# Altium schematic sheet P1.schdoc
size 178 x 97 mm; Symbol: Drawing-Symbol_A4; Company: 嘉立创EDA; Version: V1.0; Page Size: A4; @Project Name: PCB; @Update Date: 2026-07-19; @Create Date: 2026-07-19; Device: Drawing-Symbol_A4; @Board Name: Board1; @Page Name: P1; @Create Time: 23:37:44; @Page Count: 1; @Page No: 1; @Schematic Name: Schematic1; @Update Time: 23:37:44; @Assembly Variant: Basic; Border: 0; Title Block Position: 3; Size: A4; Width: 1170; Height: 825; Region Start: 1; X Region Count: 6; Y Region Count: 4; Blade Width: 10
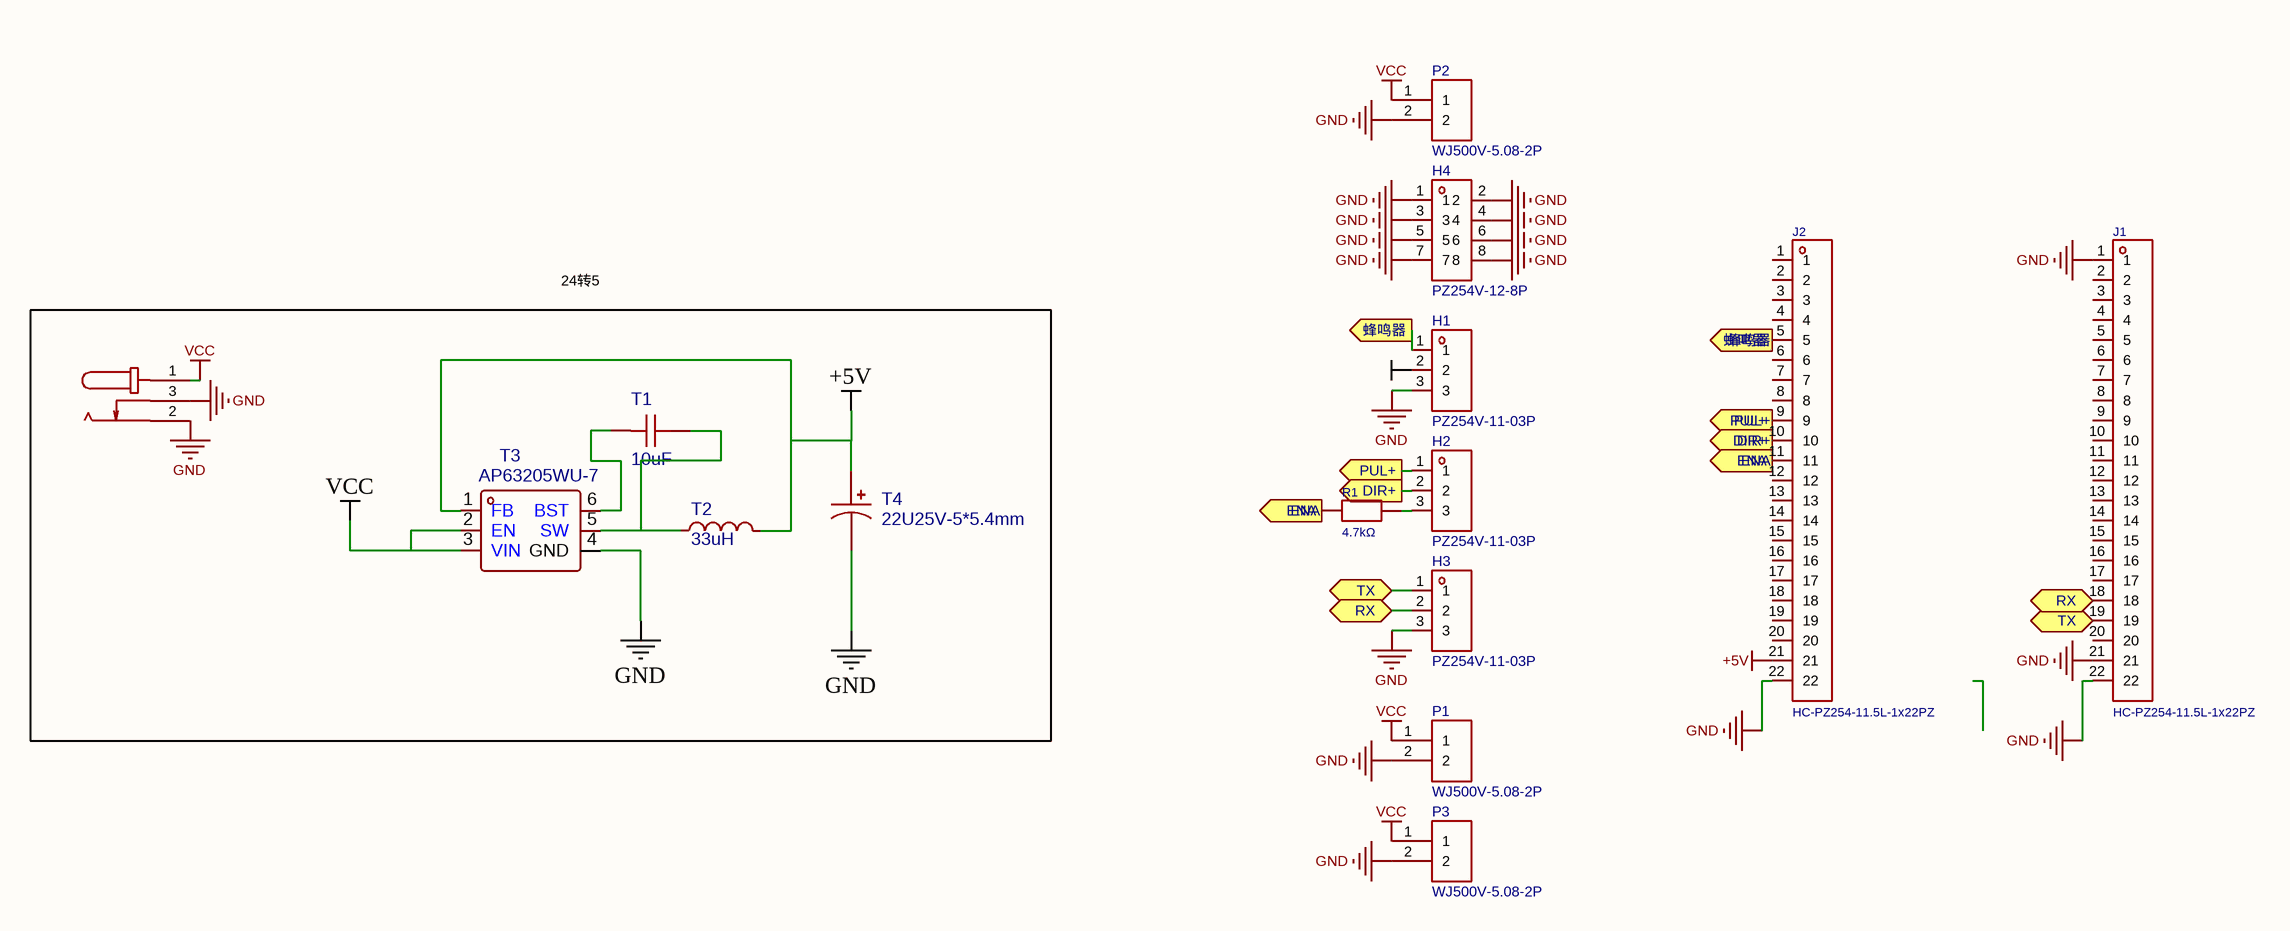
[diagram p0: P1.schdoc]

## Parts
DC1  DC005  [DC-IN-TH_DC005]  (value not drawn)
H1  PZ254V-11-03P  [HDR-TH_3P-P2.54-V-M_PZ254V-11-03P]
H2  PZ254V-11-03P  [HDR-TH_3P-P2.54-V-M_PZ254V-11-03P]
H3  PZ254V-11-03P  [HDR-TH_3P-P2.54-V-M_PZ254V-11-03P]
H4  PZ254V-12-8P  [HDR-TH_8P-P2.54-V-M-R2-C4-S2.54]
J1  HC-PZ254-11.5L-1x22PZ  [HDR-TH_22P-P2.54-V-M]
J2  HC-PZ254-11.5L-1x22PZ  [HDR-TH_22P-P2.54-V-M]
P1  WJ500V-5.08-2P  [CONN-TH_2P-P5.00_WJ500V-5.08-2P]
P2  WJ500V-5.08-2P  [CONN-TH_2P-P5.00_WJ500V-5.08-2P]
P3  WJ500V-5.08-2P  [CONN-TH_2P-P5.00_WJ500V-5.08-2P]
R1  4.7kΩ  [R0603]
T1  10uF  [C0603]
T2  33uH  [IND-SMD_L7.0-W6.6_FXL0650]
T3  AP63205WU-7  [TSOT-23-6_L2.9-W1.6-P0.95-LS2.8-BL]
T4  22U25V-5*5.4mm  [CAP-SMD_BD5.0-L5.3-W5.3-LS6.0-FD]

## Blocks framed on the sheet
24转5: DC1 T1-T4

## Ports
DIR+ (out), ENA (out), PUL+ (out), RX (bidir), TX (bidir), 蜂鸣器 (out)

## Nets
+5V: J2.21 T2.2 T3.1(FB) T4.1
GND: DC1.2 DC1.3 H1.3 H3.3 H4.1 H4.2 H4.3 H4.4 H4.5 H4.6 H4.7 H4.8 J1.1 J1.21 J1.22 J2.22 P1.2 P2.2 P3.2 T3.4(GND) T4.2
VCC: DC1.1 P1.1 P2.1 P3.1 T3.2(EN) T3.3(VIN)
DIR+: H2.2 J2.10 ; port DIR+
ENA: J2.11 R1.1 ; port ENA
PUL+: H2.1 J2.9 ; port PUL+
RX: H3.2 J1.18 ; port RX
TX: H3.1 J1.19 ; port TX
蜂鸣器: H1.1 J2.5 ; port 蜂鸣器
NetH2_3: H2.3 R1.2
NetT1_1: T1.1 T2.1 T3.5(SW)
NetT1_2: T1.2 T3.6(BST)

Not connected (* = marked no-connect by the designer): H1 2; J1 2 3 4 5 6 7 8 9 10 11 12 13 14 15 16 17 20; J2 1 2 3 4 6 7 8 12 13 14 15 16 17 18 19 20

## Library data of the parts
DC1 = DC005: 连接器类型:DC电源插座;安装方式:弯插;触点内径:2mm;触点外径:6.3mm;额定电流:500mA;额定电压:12V;工作温度:-30℃~+70℃;; Manufacturer: SHOU HAN(首韩); Symbol: DC005_C431533; Add into BOM: yes; 3D Model Transform: 366.141,553.149,0,270,0,0,-141.734,88.583,-149.606; 3D Model: f168fe383f964e0ea2af0127ff6ac7b4; Connector Type: DC电源插座; Inside Contact Diameter: 2mm; Outside Contact Diameter: 6.3mm; Current Rating: 500mA; Voltage Rating (Max): 12V
H1-H3 = PZ254V-11-03P: 插针结构:1x3P;间距:2.54mm;行距:-;圆针/方针:方针;安装方式:直插;排数:单排;总PIN位数:3P;额定电流:3A;额定电压:250V;配合针长度:6mm;塑高:2.5mm;端接针长度:3mm;工作温度:-40℃~+105℃;颜色:黑色;; Manufacturer: XFCN(兴飞); Symbol: PZ254V-11-03P_C2937625; AddInBom: yes; ModelId: bd28a638fbd247be9398fd5d39c366ec0819f05c4eef4c71ace90d822a990e87; ModelTransform: 300.3931,100,0,0,0,0,0,0,-118.11; Pin Structure: 1x3P; Pitch: 2.54mm; Circluar Pins/Square Pins: 方针; Current Rating: 3A; Voltage Rating (Max): 250V
H4 = PZ254V-12-8P: 插针结构:2x4P;间距:2.54mm;行距:2.54mm;圆针/方针:方针;安装方式:直插;排数:双排;总PIN位数:8P;额定电流:-;额定电压:-;配合针长度:6mm;塑高:2.5mm;端接针长度:3mm;触头材质:黄铜;触头镀层:-;工作温度:-40℃~+105℃;颜色:黑色;; Manufacturer: XFCN(兴飞); AddInBom: yes; ModelId: 9655140a9899454ea9d6a6732d55fb0e0819f05c4eef4c71ace90d822a990e87; ModelName: HDR-TH_8P-P2.54-M-LI-2X4P; ModelTransform: 399.999,200,0,0,0,0,0,0,-118.11; Pin Structure: 2x4P; Pitch: 2.54mm; Circluar Pins/Square Pins: 方针
J1 J2 = HC-PZ254-11.5L-1x22PZ: 插针结构:1x22P;间距:2.54mm;行距:-;圆针/方针:方针;安装方式:直插;排数:单排;总PIN位数:22P;额定电流:3A;额定电压:-;配合针长度:6mm;塑高:2.5mm;端接针长度:3mm;触头材质:黄铜;触头镀层:金;工作温度:-40℃~+105℃;颜色:黑色;; Manufacturer: HC(虹成电子); Add into BOM: yes; 3D Model: 875f4c094945453e8148e92095c9b8a7; 3D Model Transform: 2199.99552,98.425,0,0,0,0,0,0,-118.11; Pin Structure: 1x22P; Pitch: 2.54mm; Circluar Pins/Square Pins: 方针; Current Rating: 3A; ModelName: HDR-TH_22P-P2.54-M-LI-1X22P
P1 = WJ500V-5.08-2P: 结构:1x2P;间距:5.08mm;颜色:绿色;安装方式:直插;额定电流:18A;额定电压:250V;排数:1;线规 - AWG:14~30;线规 - 平方毫米:2.5;每排PIN数:2;触头材质:-;触头镀层:-;工作温度范围:-40℃~+105℃;焊接温度(最大值):-;; Manufacturer: KANGNEX(康奈克斯电气); Symbol: WJ500V-5.08-2P-14-00A; AddInBom: yes; ModelId: 0f4a503c8d3b4ae19ed61267f5e9a1d70819f05c4eef4c71ace90d822a990e87; ModelTransform: 423.621,393.7,0,0,0,0,-11.811,19.685,-137.795; Structure: 1x2P; Pitch: 5.08mm; Current Rating (Max): 18A; Voltage Rating (Max): 250V; Wire Gauge - AWG: 14~30; Wire Gauge - mm2: 2.5; Number of PINs Per Row: 2; Screw Specification: M2.5
P2 P3 = WJ500V-5.08-2P: 结构:1x2P;间距:5.08mm;颜色:绿色;安装方式:直插;额定电流:18A;额定电压:250V;排数:1;线规 - AWG:14~30;线规 - 平方毫米:2.5;每排PIN数:2;触头材质:-;触头镀层:-;工作温度范围:-40℃~+105℃;焊接温度(最大值):-;; Manufacturer: KANGNEX(康奈克斯电气); Symbol: WJ500V-5.08-2P-14-00A; 3D Model: 0f4a503c8d3b4ae19ed61267f5e9a1d70819f05c4eef4c71ace90d822a990e87; 3D Model Transform: 423.621,393.7,0,0,0,0,-11.811,19.685,-137.795; Structure: 1x2P; Pitch: 5.08mm; Current Rating (Max): 18A; Voltage Rating (Max): 250V; Wire Gauge - AWG: 14~30; Wire Gauge - mm2: 2.5; Number of PINs Per Row: 2; Screw Specification: M2.5; AddInBom: yes
R1 = FRR0603F4701TS: 电阻类型:厚膜电阻;阻值:4.7kΩ;精度:±1%;功率:100mW;工作电压:75V;温度系数:±100ppm/℃;; Manufacturer: FOJAN(富捷); AddInBom: yes; ModelId: fc143cca1e79419f9cd78b61e9279f080819f05c4eef4c71ace90d822a990e87; ModelTransform: 31.8897,63.7794,0,90,0,0,0,0,0; Tolerance: ±1%; Power(Watts): 100mW; Voltage-Supply(Max): 75V
T1 = 0603X106M100CT: 容值:10uF;精度:±20%;额定电压:10V;温度系数:X5R;; Manufacturer: Walsin(华新科); Add into BOM: yes; 3D Model Transform: 62.992,31.496,0,0,0,0,0,0,0; 3D Model: ac125912035d415993ca9572d50418b1; Tolerance: ±20%; Voltage Rating: 10V; Temperature Coefficient: X5R; ModelName: C0603_L1.6-W0.8-H0.8
T2 = FXL0650-330-M: 电感值:33uH;精度:±20%;额定电流:2.3A;饱和电流(Isat):3A;类型:一体成型电感;; Manufacturer: cjiang(长江微电); Add into BOM: yes; 3D Model Transform: 275.59,259.842,0,0,0,0,0,0,0; 3D Model: 79e71cf45778409db1a3f3d6d59bfe87; Tolerance: ±20%; Current Rating: 2.3A; Current - Saturation(Isat): 3A; DC Resistance(DCR): 190mΩ; Type: 一体成型电感; ModelName: IND-SMD_L7.0-W6.6-H4.8_FXL0650
T3 = AP63205WU-7: Manufacturer: DIODES(美台); Add into BOM: yes; Origin 3D Model Title: TSOT-23-6_L2.9-W1.6-H1.1-LS2.8-P0.95; 3D Model Transform: 110.236,114.173,0,90,0,0,0.001,-0.001,0
T4 = 22U25V-5*5.4mm: Add into BOM: yes; 3D Model Transform: 236.22,208.661,0,0,0,0,-0.001,-0.003,0; 3D Model: ed942b427de741e3aabba01c64b2d723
